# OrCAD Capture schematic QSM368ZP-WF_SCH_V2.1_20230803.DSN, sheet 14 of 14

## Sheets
14 PAGE07-Mini-PCIE/C: size A2
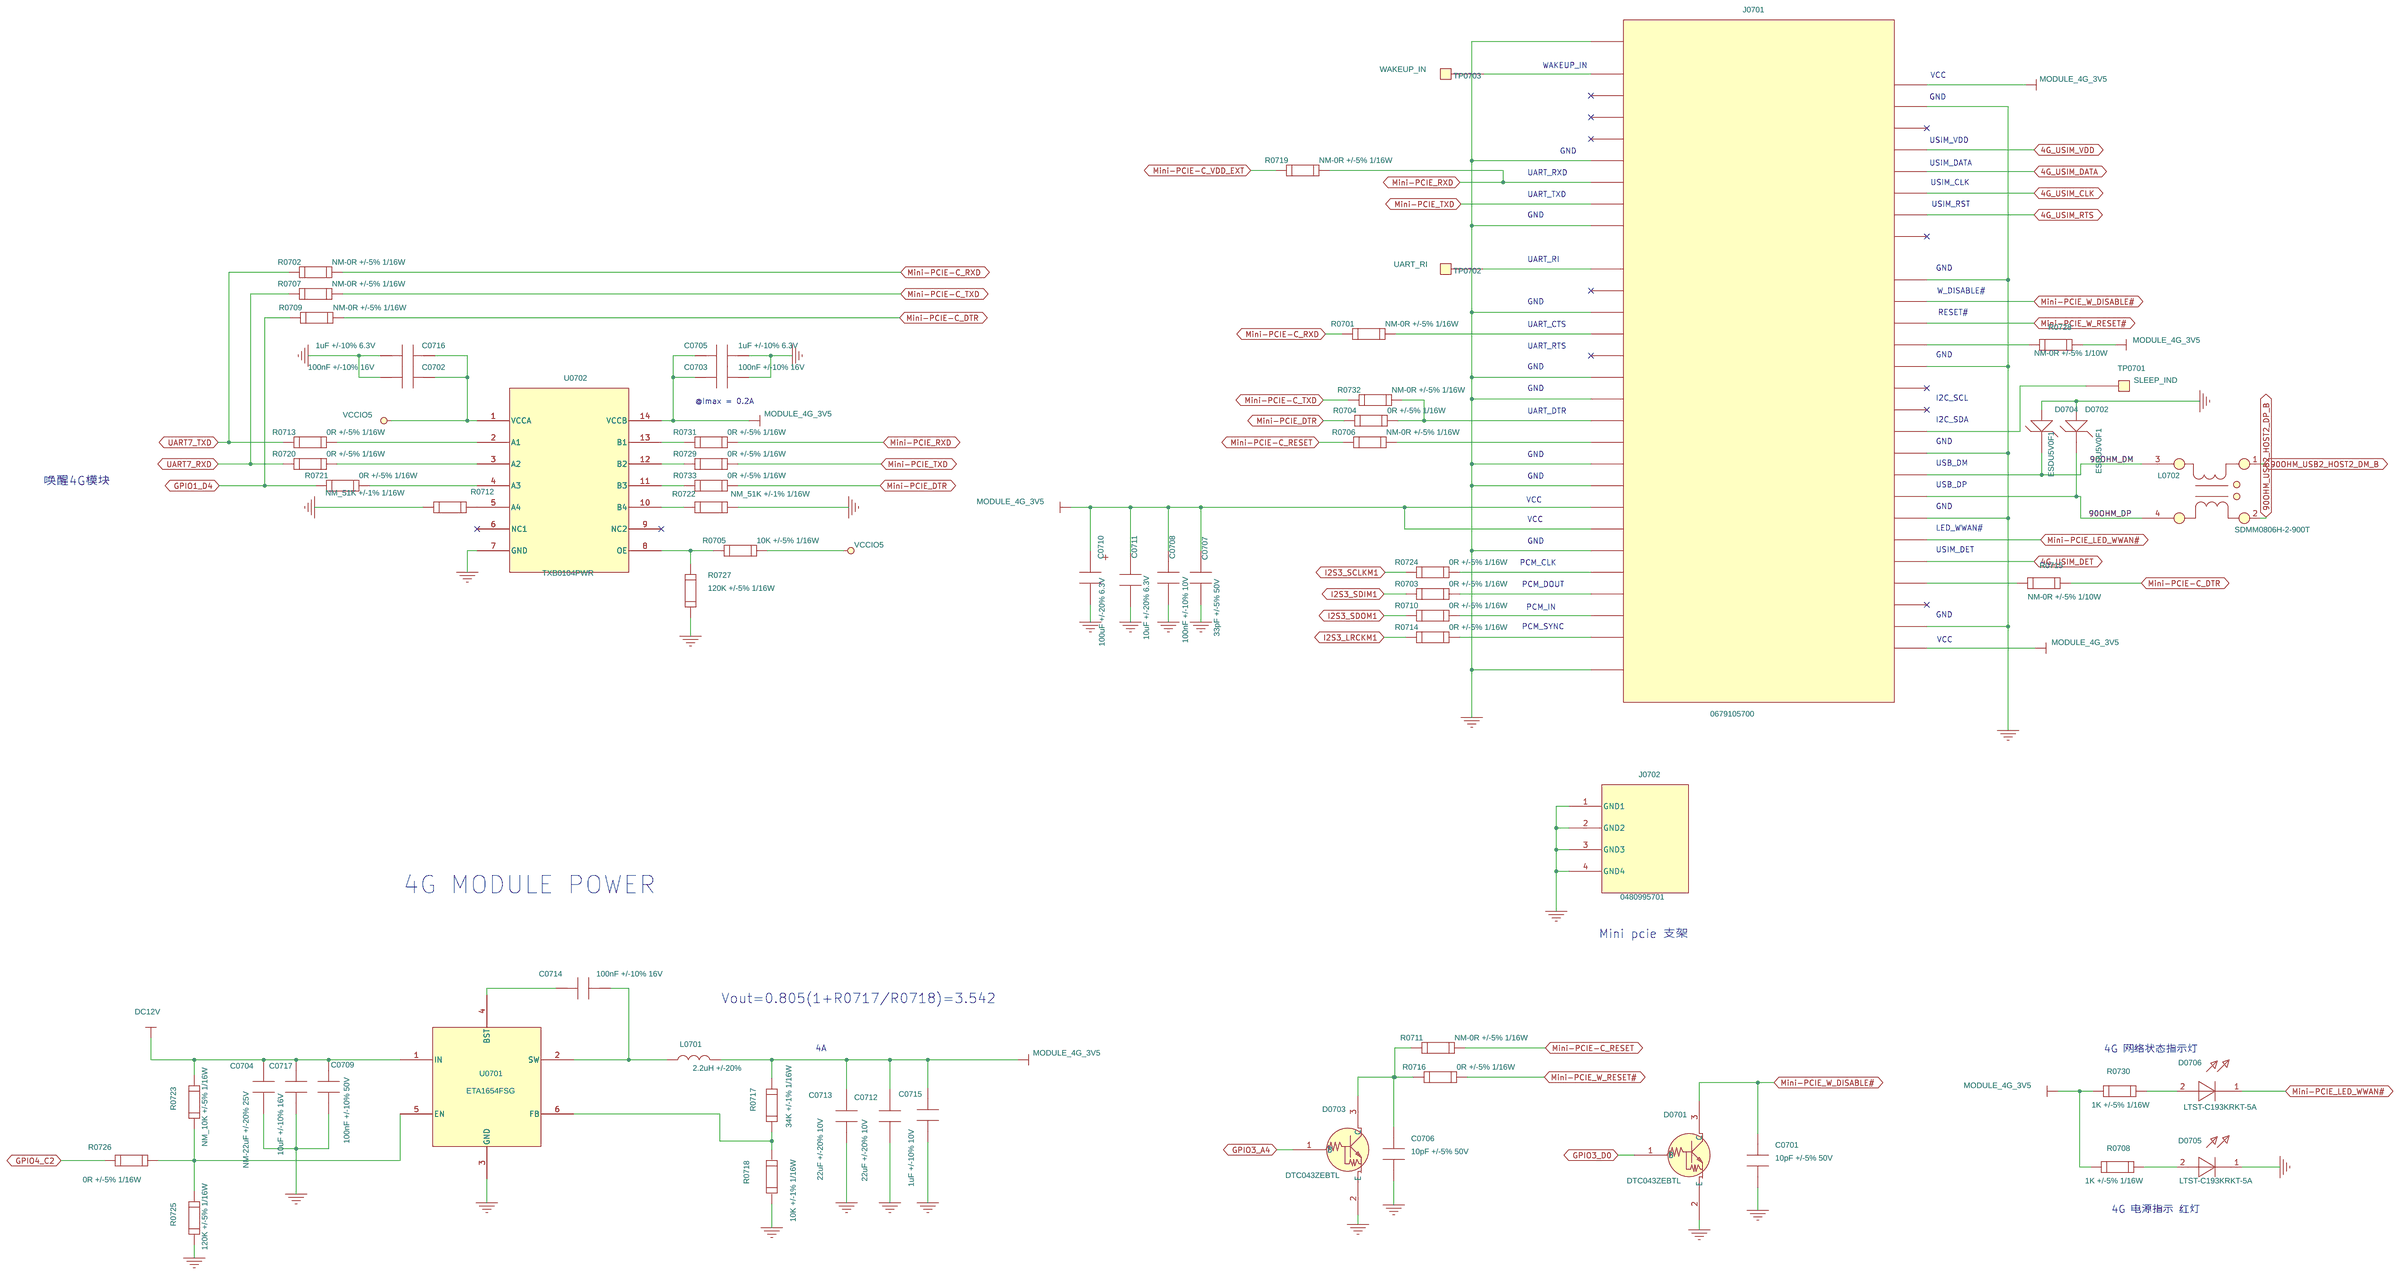
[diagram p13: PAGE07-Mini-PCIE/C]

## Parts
C0701  10pF +/-5% 50V  [C-0402]
C0702  100nF +/-10% 16V  [C-0402]
C0703  100nF +/-10% 16V  [C-0402]
C0704  NM-22uF +/-20% 25V  [C-0805_H1_45]
C0705  1uF +/-10% 6.3V  [C-0402]
C0706  10pF +/-5% 50V  [C-0402]
C0707  33pF +/-5% 50V  [C-0402]
C0708  100nF +/-10% 10V  [C-0402]
C0709  100nF +/-10% 50V  [C-0603]
C0710  100uF +/-20% 6.3V  [3528TB-M]
C0711  10uF +/-20% 6.3V  [c-0402_4_7_10uf]
C0712  22uF +/-20% 10V  [c-0603_22_47uf_h1_00]
C0713  22uF +/-20% 10V  [c-0603_22_47uf_h1_00]
C0714  100nF +/-10% 16V  [C-0402]
C0715  1uF +/-10% 10V  [C-0402]
C0716  1uF +/-10% 6.3V  [C-0402]
C0717  10uF +/-10% 16V  [C-0805_H1_45]
D0701  DTC043ZEBTL  [DTC043ZEBTL]
D0702  ESDU5V0F1  [ESDU5V0F1]
D0703  DTC043ZEBTL  [DTC043ZEBTL]
D0704  ESDU5V0F1  [ESDU5V0F1]
D0705  LTST-C193KRKT-5A  [LTST-C193KRKT-5A]
D0706  LTST-C193KRKT-5A  [LTST-C193KRKT-5A]
J0701  0679105700  [MINI-PCIE-CON]
J0702  0480995701  [480995701]
L0701  2.2uH +/-20%  [L-SPM6530T-3R3M]
L0702  SDMM0806H-2-900T  [SDMM0806H-2-900T]
R0701  NM-0R +/-5% 1/16W  [R-0402]
R0702  NM-0R +/-5% 1/16W  [R-0402]
R0703  0R +/-5% 1/16W  [R-0402]
R0704  0R +/-5% 1/16W  [R-0402]
R0705  10K +/-5% 1/16W  [R-0402]
R0706  NM-0R +/-5% 1/16W  [R-0402]
R0707  NM-0R +/-5% 1/16W  [R-0402]
R0708  1K +/-5% 1/16W  [R-0402]
R0709  NM-0R +/-5% 1/16W  [R-0402]
R0710  0R +/-5% 1/16W  [R-0402]
R0711  NM-0R +/-5% 1/16W  [R-0402]
R0712  NM_51K +/-1% 1/16W  [R-0402]
R0713  0R +/-5% 1/16W  [R-0402]
R0714  0R +/-5% 1/16W  [R-0402]
R0715  NM-0R +/-5% 1/10W  [R-0603]
R0716  0R +/-5% 1/16W  [R-0402]
R0717  34K +/-1% 1/16W  [R-0402]
R0718  10K +/-1% 1/16W  [R-0402]
R0719  NM-0R +/-5% 1/16W  [R-0402]
R0720  0R +/-5% 1/16W  [R-0402]
R0721  0R +/-5% 1/16W  [R-0402]
R0722  NM_51K +/-1% 1/16W  [R-0402]
R0723  NM_10K +/-5% 1/16W  [R-0402]
R0724  0R +/-5% 1/16W  [R-0402]
R0725  120K +/-5% 1/16W  [R-0402]
R0726  0R +/-5% 1/16W  [R-0402]
R0727  120K +/-5% 1/16W  [R-0402]
R0728  NM-0R +/-5% 1/10W  [R-0603]
R0729  0R +/-5% 1/16W  [R-0402]
R0730  1K +/-5% 1/16W  [R-0402]
R0731  0R +/-5% 1/16W  [R-0402]
R0732  NM-0R +/-5% 1/16W  [R-0402]
R0733  0R +/-5% 1/16W  [R-0402]
TP0701  SLEEP_IND  [TP_1_00]
TP0702  UART_RI  [TP_1_00]
TP0703  WAKEUP_IN  [TP_1_00]
U0701  ETA1654FSG  [ETA1654FSG]
U0702  TXB0104PWR  [TXB0104PWR]

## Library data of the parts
C0701 C0706 = C: Application_Level: Limited(限制); DataRecord: 2017-08-09; Geometry Height: 0.5mm; Lib_Name: 电容; MPN: CC0402JRNPO9BN100; Manufacturer: YAGEO; Part Description: CAP C0G 10pF +/-5% 50V CH0402 H0.55mm RO; Part Number: QT0012100646; Rev.Date: 2021-12-15
C0702 C0703 = C: Application_Level: Non-common(非通用); DataRecord: 2017-08-09; Geometry Height: 0.5mm; Lib_Name: 电容; MPN: CC0402KRX7R7BB104; Manufacturer: YAGEO; Part Description: CAP X7R 100nF +/-10% 16V CH0402 H0.55mm RO; Part Number: QT0012100748; Rev.Date: 2021-12-15
C0704 = C-0805_H1_45: Application_Level: Limited(限制); BOMRemark: NM; DataRecord: 2020-01-09; Geometry Height: 1.45mm; Lib_Name: 电容; MPN: GRM21BR61E226ME44L; Manufacturer: MURATA; Part Description: CAP X5R 22uF +/-20% 25V CH0805 H1.45mm RO; Part Number: QT0012002582; Rev.Date: 2021-10-25
C0705 C0716 = C: Application_Level: Common(通用); DataRecord: 2017-08-09; Geometry Height: 0.5mm; Lib_Name: 电容; MPN: CC0402KRX5R5BB105; Manufacturer: YAGEO; Part Description: CAP X5R 1uF +/-10% 6.3V CH0402 H0.55mm RO; Part Number: QT0012100534; Rev.Date: 2021-12-15
C0707 = C: Application_Level: Non-common(非通用); DataRecord: 2017-08-09; Geometry Height: 0.5mm; Lib_Name: 电容; MPN: CC0402JRNPO9BN330; Manufacturer: YAGEO; Part Description: CAP C0G 33pF +/-5% 50V CH0402 H0.55mm RO; Part Number: QT0012100261; Rev.Date: 2022-08-17
C0708 = C: Application_Level: Common(通用); DataRecord: 2017-08-09; Geometry Height: 0.5mm; Lib_Name: 电容; MPN: CC0402KRX7R6BB104; Manufacturer: YAGEO; Part Description: CAP X7R 100nF +/-10% 10V CH0402 H0.55mm RO; Part Number: QT0012000328; Rev.Date: 2022-08-17
C0709 = C: Application_Level: Non-common(非通用); DataRecord: 2017-08-09; Geometry Height: 0.8mm; Lib_Name: 电容; MPN: CC0603KRX7R9BB104; Manufacturer: YAGEO; Part Description: CAP X7R 100nF +/-10% 50V CH0603 H0.9mm RO; Part Number: QT0012000587; Rev.Date: 2022-08-17
C0710 = C-3528TB-M: DataRecord: 2017-12-12; Geometry Height: 2.1mm; MPN: TCOB0J107M8R-ES1; Manufacturer: ROHM; Part Description: CAP STA Polymer 100uF +/-20% 6.3V ESR=0.045R B CASE 3.5x2.8mm H2.1mm RO; Part Number: QT0012002189; Rev.Date: 2022-09-21; SCH Part: C-TCOB0J107M8R
C0711 = C-0402_X5R_10UF: DataRecord: 2017-08-09; Geometry Height: 0.5mm; MPN: CC0402MRX5R5BB106; Part Description: CAP X5R 10uF +/-20% 6.3V CH0402 H0.7mm RO; Rev.Date: 2022-08-17; SCH Part: c-0402_4_7_10uf_H0_70
C0712 C0713 = c-0603_22_47uf_H1_00: Application_Level: 通用; DataRecord: 2017-08-09; Geometry Height: 1.0mm; Lib_Name: 电容; MPN: CC0603MRX5R6BB226; Manufacturer: YAGEO; Part Description: CAP X5R 22uF +/-20% 10V CH0603 1.6x0.8mm H1mm RO; Part Number: QT0012102005; Rev.Date: 2022-09-21
C0714 = C: Application_Level: Non-common(非通用); DataRecord: 2017-08-09; Geometry Height: 0.5mm; Lib_Name: 电容; MPN: CC0402KRX7R7BB104; Manufacturer: YAGEO; Part Description: CAP X7R 100nF +/-10% 16V CH0402 H0.55mm RO; Part Number: QT0012100748; Rev.Date: 2022-08-17
C0715 = C: Application_Level: 通用; DataRecord: 2017-08-09; Geometry Height: 0.5mm; Lib_Name: 电容; MPN: CC0402KRX5R6BB105; Manufacturer: YAGEO; Part Description: CAP X5R 1uF +/-10% 10V CH0402 H0.55mm RO; Part Number: QT0012000349; Rev.Date: 2022-08-17
C0717 = C-0805_H1_45: Application_Level: Common(通用); DataRecord: 2017-08-09; Geometry Height: 1.45mm; Lib_Name: 电容; MPN: CC0805KKX5R7BB106; Manufacturer: YAGEO; Part Description: CAP X5R 10uF +/-10% 16V CH0805 2.0x1.25mm H1.45mm RO; Part Number: QT0012001358; Rev.Date: 2022-09-21
D0701 D0703 = DTC043ZEBTL: Application_Level: Common(通用); DataRecord: 2017-08-09; Geometry Height: 0.6mm; Lib_Name: 三极管; Manufacturer: ROHM; Part Description: AUD Digital NPN 50V 100mA R1=4.7K R2=47K EMT3F RO; Part Number: QT0015200080; Rev.Date: 2021-12-15
D0702 D0704 = ESDU5V0F1: Application_Level: Common(通用); DataRecord: 2017-08-09; Geometry Height: 0.5mm; Lib_Name: ESD&EMI&TVS; Manufacturer: JCET; Part Description: TVS Si Vrwm=5V 0.5pF 1.0x0.6mm H0.5mm RO; Part Number: QT0013500188; Rev.Date: 2023-02-08
D0705 D0706 = LTST-C193KRKT-5A: Application_Level: Common(通用); DataRecord: 2017-08-09; Geometry Height: 0.35mm; Lib_Name: LED; Manufacturer: LITEON; Part Description: DIO LED RED VF=2.0V CH0603 RO; Part Number: QT0015300052; Rev.Date: 2022-03-31
J0701 = MINI-PCIE-CON: Application_Level: 限制（Others）; DataRecord: 2019-12-03; Geometry Height: 5.75mm; Lib_Name: 结构连接器; Manufacturer: MOLEX; Part Description: CON MINIPCIE 52pin 0.8pitch H5.75mm RO; Part Number: QT0016201153; Rev.Date: 2022-08-17
J0702 = 480995701: Application_Level: 限制（Others）; DataRecord: 2021-01-13; Geometry Height: 5.2mm; Lib_Name: 结构连接器; Manufacturer: MOLEX; Part Description: CON MINI PCIE 52PIN 0.8pitch H5.2mm RO; Part Number: QT0016201412; Rev.Date: 2022-08-17
L0701 = L: Application_Level: Common(通用); DataRecord: 2023-04-12; Lib_Name: 电感&磁珠; MPN: AIP0630MB-2R2M; Manufacturer: INPAQ; Part Description: IND LOW 2.2uH +/-20% 0.015ohm 8.0A 7.0x6.6mm H3.0mm RO; Part Number: QT0014104151; Rev.Date: 2023-04-21
L0702 = SDMM0806H-2-900T: Application_Level: Common(通用); DataRecord: 2020-03-25; Geometry Height: 0.45mm; Lib_Name: ESD&EMI&TVS; Manufacturer: SUNLORD; Part Description: EMI SIN 100MHz 90R 2line 0.85X0.65mm H0.45mm RO; Part Number: QT0013501085; Rev.Date: 2022-01-10
R0701 R0702 R0706 R0707 R0709 R0711 R0719 R0732 = R-0402: Application_Level: Common(通用); BOMRemark: NM; DataRecord: 2017-08-09; Geometry Height: 0.4MM; Lib_Name: 电阻; MPN: RC0402JR-070RL; Manufacturer: YAGEO; Part Description: RES MF 0R +/-5% 1/16W CH0402 H0.4mm RO; Part Number: QT0011000094; Rev.Date: 2021-12-15
R0703 R0704 R0710 R0713 R0714 R0716 R0720 R0721 R0724 R0729 R0731 R0733 = R-0402: Application_Level: Common(通用); DataRecord: 2017-08-09; Geometry Height: 0.4MM; Lib_Name: 电阻; MPN: RC0402JR-070RL; Manufacturer: YAGEO; Part Description: RES MF 0R +/-5% 1/16W CH0402 H0.4mm RO; Part Number: QT0011000094; Rev.Date: 2021-12-15
R0705 = R-0402: Application_Level: Common(通用); DataRecord: 2017-08-09; Geometry Height: 0.4MM; Lib_Name: 电阻; MPN: RC0402JR-0710KL; Manufacturer: YAGEO; Part Description: RES MF 10K +/-5% 1/16W CH0402 H0.4mm RO; Part Number: QT0011000453; Rev.Date: 2021-12-15
R0708 R0730 = R-0402: Application_Level: Common(通用); DataRecord: 2017-08-09; Geometry Height: 0.4MM; Lib_Name: 电阻; MPN: RC0402JR-071KL; Manufacturer: YAGEO; Part Description: RES MF 1K +/-5% 1/16W CH0402 H0.4mm RO; Part Number: QT0011000489; Rev.Date: 2021-12-15
R0712 R0722 = R-0402: Application_Level: 通用; BOMRemark: NM; DataRecord: 2017-08-09; Geometry Height: 0.4MM; Lib_Name: 电阻; MPN: RC0402FR-0751KL; Manufacturer: YAGEO; Part Description: RES MF 51K +/-1% 1/16W CH0402 H0.4mm RO; Part Number: QT0011000648; Rev.Date: 2022-08-17
R0715 R0728 = R-0603: Application_Level: 通用; BOMRemark: NM; DataRecord: 2017-08-09; Geometry Height: 0.55MM; Lib_Name: 电阻; MPN: RC0603JR-070RL; Manufacturer: YAGEO; Part Description: RES MF 0R +/-5% 1/10W CH0603 H0.55mm RO; Part Number: QT0011000610; Rev.Date: 2022-08-17
R0717 = R-0402: Application_Level: 通用; DataRecord: 2017-08-09; Geometry Height: 0.4MM; Lib_Name: 电阻; MPN: RC0402FR-0734KL; Manufacturer: YAGEO; Part Description: RES MF 34K +/-1% 1/16W CH0402 H0.4mm RO; Part Number: QT0011003085; Rev.Date: 2022-08-17
R0718 = R-0402_v3: Application_Level: 通用; DataRecord: 2017-08-09; Geometry Height: 0.4MM; Lib_Name: 电阻; MPN: RC0402FR-0710KL; Manufacturer: YAGEO; Part Description: RES MF 10K +/-1% 1/16W CH0402 H0.4mm RO; Part Number: QT0011000594; Rev.Date: 2022-08-17
R0723 = R-0402: Application_Level: Common(通用); BOMRemark: NM; DataRecord: 2017-08-09; Geometry Height: 0.4MM; Lib_Name: 电阻; MPN: RC0402JR-0710KL; Manufacturer: YAGEO; Part Description: RES MF 10K +/-5% 1/16W CH0402 H0.4mm RO; Part Number: QT0011000453; Rev.Date: 2022-08-17
R0725 = R-0402: Application_Level: 通用; DataRecord: 2017-08-09; Geometry Height: 0.4MM; Lib_Name: 电阻; MPN: RC0402JR-07120KL; Manufacturer: YAGEO; Part Description: RES MF 120K +/-5% 1/16W CH0402 H0.4mm RO; Part Number: QT0011000521; Rev.Date: 2022-08-17
R0726 = R-0402: Application_Level: 通用; DataRecord: 2017-08-09; Geometry Height: 0.4MM; Lib_Name: 电阻; MPN: RC0402JR-070RL; Manufacturer: YAGEO; Part Description: RES MF 0R +/-5% 1/16W CH0402 H0.4mm RO; Part Number: QT0011000094; Rev.Date: 2022-08-17
R0727 = R-0402: Application_Level: Common(通用); DataRecord: 2017-08-09; Geometry Height: 0.4MM; Lib_Name: 电阻; MPN: RC0402JR-07120KL; Manufacturer: YAGEO; Part Description: RES MF 120K +/-5% 1/16W CH0402 H0.4mm RO; Part Number: QT0011000521; Rev.Date: 2021-12-15
TP0701 TP0702 TP0703 = TP: DataRecord: 2021-03-15; Geometry Height: 0.1mm; Lib_Name: 其他; Manufacturer: QUECTEL; Remark: Origin Imported on 2020/6/12; Rev.Date: 2021-03-15; option: @
U0701 = ETA1654FSG: Application_Level: 通用; DataRecord: 2021-11-26; Geometry Height: 0.6mm; Lib_Name: 电源管理芯片; Manufacturer: ETA; Part Description: PMIC DC-DC BUCK 4.5-18V ADJ 600KHz 4A 230uA SOT-563-6 1.6x1.6mm H0.6mm RO; Part Number: QT0013101598; Rev.Date: 2022-08-17
U0702 = TXB0104PWR: Application_Level: Non-common(非通用); DataRecord: 2020-04-16; Geometry Height: 1.75mm; Lib_Name: 驱动芯片; Manufacturer: TI; Part Description: IC 4-BIT BIDIRECTIONAL VOLTAGE-LEVEL TRANSLATOR TSSOP-14 RO; Part Number: QT0013901218; Rev.Date: 2021-12-15

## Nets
GND: C0701.1 C0702.2 C0703.2 C0704.1 C0705.2 C0706.1 C0707.1 C0708.1 C0709.1 C0710.2 C0711.1 C0712.1 C0713.1 C0715.1 C0716.2 C0717.1 D0701.2(E) D0702.2 D0703.2(E) D0704.2 D0705.1 J0701.4 J0701.9 J0701.15 J0701.18 J0701.21 J0701.26 J0701.27 J0701.29 J0701.34 J0701.35 J0701.37 J0701.40 J0701.43 J0701.50 J0701.53 J0701.54 J0702.1(GND1) J0702.2(GND2) J0702.3(GND3) J0702.4(GND4) R0712.1 R0718.1 R0722.2 R0725.1 R0727.1 U0701.3(GND) U0702.7(GND) ; also on sheet 1 2 3 4 5 6 7 8 9 10 11 12 13
VCCIO5: C0702.1 C0716.1 R0705.2 U0702.1(VCCA) ; also on sheet 9 10 12
4G_USIM_CLK: J0701.12 ; also on sheet 7
4G_USIM_DATA: J0701.10 ; also on sheet 7
4G_USIM_DET: J0701.44 ; also on sheet 7
4G_USIM_RTS: J0701.14 ; also on sheet 7
4G_USIM_VDD: J0701.8 ; also on sheet 7
90OHM_DM: D0704.1 J0701.36 L0702.3
90OHM_DP: D0702.1 J0701.38 L0702.4
90OHM_USB2_HOST2_DM_B: L0702.1 ; also on sheet 6
90OHM_USB2_HOST2_DP_B: L0702.2 ; also on sheet 6
DC12V: C0704.2 C0709.2 C0717.2 R0723.2 U0701.1(IN) ; also on sheet 1 5 6 9
GPIO1_D4: R0709.1 R0721.1 ; also on sheet 12
GPIO3_A4: D0703.1(B) ; also on sheet 11 12
GPIO3_D0: D0701.1(B) ; also on sheet 12
GPIO4_C2: R0726.1 ; also on sheet 12
I2S3_LRCKM1: R0714.1 ; also on sheet 12
I2S3_SCLKM1: R0724.1 ; also on sheet 12
I2S3_SDIM1: R0703.1 ; also on sheet 12
I2S3_SDOM1: R0710.1 ; also on sheet 12
Mini-PCIE-C_DTR: R0709.2 R0715.2
Mini-PCIE-C_RESET: R0706.1 R0711.2
Mini-PCIE-C_RXD: R0701.1 R0702.2
Mini-PCIE-C_TXD: R0707.2 R0732.1
Mini-PCIE-C_VDD_EXT: R0719.1 ; also on sheet 7
Mini-PCIE_DTR: R0704.1 R0733.2
Mini-PCIE_LED_WWAN#: D0706.1 J0701.42
Mini-PCIE_RXD: J0701.11 R0719.2 R0731.2
Mini-PCIE_TXD: J0701.13 R0729.2
Mini-PCIE_W_DISABLE#: C0701.2 D0701.3(C) J0701.20
Mini-PCIE_W_RESET#: J0701.22 R0716.2
MODULE_4G_3V5: C0703.1 C0705.1 C0707.2 C0708.2 C0710.1 C0711.2 C0712.2 C0713.2 C0715.2 J0701.2 J0701.39 J0701.41 J0701.52 L0701.2 R0708.1 R0717.2 R0728.2 R0730.1 U0702.14(VCCB)
UART7_RXD: R0707.1 R0720.1 ; also on sheet 12
UART7_TXD: R0702.1 R0713.1 ; also on sheet 12
N16421517: D0706.2 R0730.2
N16421911: D0705.2 R0708.2
N17980948: R0723.1 R0725.2 R0726.2 U0701.5(EN)
N17980958: C0714.2 U0701.4(BST)
N17980968: C0714.1 L0701.1 U0701.2(SW)
N17981000: R0717.1 R0718.2 U0701.6(FB)
N19332658: J0701.17 TP0702.1
N19332747: J0701.1 TP0703.1
N19347845: R0731.1 U0702.13(B1)
N19347847: R0729.1 U0702.12(B2)
N19347865: R0705.1 R0727.2 U0702.8(OE)
N19347930: R0713.2 U0702.2(A1)
N19349212: R0720.2 U0702.3(A2)
N19352428: J0701.45 R0724.2
N19352448: J0701.47 R0703.2
N19352470: J0701.49 R0710.2
N19352490: J0701.51 R0714.2
N19352717: C0706.2 D0703.3(C) R0711.1 R0716.1
N19354367: J0701.23 R0701.2
N19354450: J0701.31 R0704.2 R0732.2
N19356842: J0701.33 R0706.2
N19357290: J0701.24 R0728.1
N19357904: J0701.32 TP0701.1
N19358667: R0721.2 U0702.4(A3)
N19358768: R0733.1 U0702.11(B3)
N19359275: J0701.46 R0715.1
N19367635: R0722.1 U0702.10(B4)
N19371999: R0712.2 U0702.5(A4)

Not connected (* = marked no-connect by the designer): J0701 3* 5* 6* 7* 16* 19* 25* 28* 30* 48*; U0702 6(NC1)* 9(NC2)*

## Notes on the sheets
sheet 14
- WAKEUP_IN
- VCC
- GND
- USIM_VDD
- GND
- USIM_DATA
- UART_RXD
- USIM_CLK
- UART_TXD
- USIM_RST
- GND
- UART_RI
- GND
- W_DISABLE#
- GND
- RESET#
- UART_CTS
- UART_RTS
- GND
- GND
- GND
- I2C_SCL
- @Imax = 0.2A
- UART_DTR
- I2C_SDA
- GND
- GND
- USB_DM
- 唤醒4G模块
- GND
- USB_DP
- VCC
- GND
- VCC
- LED_WWAN#
- GND
- USIM_DET
- PCM_CLK
- PCM_DOUT
- PCM_IN
- GND
- PCM_SYNC
- VCC
- 4G MODULE POWER
- Mini pcie 支架
- Vout=0.805(1+R0717/R0718)=3.542
- 4A
- 4G 网络状态指示灯
- 4G 电源指示 红灯
